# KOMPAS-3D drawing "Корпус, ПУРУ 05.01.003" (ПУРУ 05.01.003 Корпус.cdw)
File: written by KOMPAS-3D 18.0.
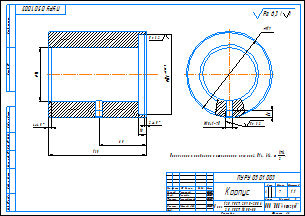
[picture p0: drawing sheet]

Sheet 1: A3, landscape

Document properties: Автор: cons; Полное имя файла: D:\Град\ПУРУ 00.00.000 Установка пусковая ручная Элия-Р\ПУРУ 05.00.000 Корпус\ПУРУ 05.01.000 Обойма\Чертежи\ПУРУ 05.01.003 Корпус.cdw; Масса: 6.98161; Параметр неуказанной шероховатости: Ra 6,3

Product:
- Part/product: Корпус  | designation ПУРУ 05.01.003
    Материал: Круг$d120 ГОСТ 2590-2006;20 ГОСТ 1050-88$ (density 7859 kg/m3)
    Масса: 6.79078
    Раздел спецификации: Детали
    Форматы листов документа: A3
    source file: ..\ПУРУ 05.01.003 Корпус.m3d, ПУРУ 05.01.003 Корпус.cdw
- Part/product: Корпус  | designation ПУРУ 05.01.003
    Материал: Круг$d120 ГОСТ 2590-2006;20 ГОСТ 1050-88$ (density 7859 kg/m3)
    Масса: 6.98161
    Раздел спецификации: Детали
    Форматы листов документа: A3

Table, sheet 1:
  0;Material:V399CD8922A934364BF9D3DB1A16B3F75;Sortament:V6A25FA24F2024846A417965BB2EC510D^SortamentEx:VAF31E2474CC111D7A5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
Title block, sheet 2: Наименование: Корпус; designation: ПУРУ 05.01.003; Материал: Круг 120 ГОСТ 2590-2006 20 ГОСТ 1050-88; Масса: 7; sheet number: 1; organisation: ООО "НПЦ"Антиград"; Форматы листов документа: A3; revision letter: А; stored path: D:\РУ 00.00.000 Установка противоградовая ручная\РУ 05.00.000 Корпус\РУ 05.01.000 Обойма\Чертежи\РУ 05.01.003 Корпус.cdw; Разработал: Грицунов; Проверил: Налоева; Т. контр.: Семеновский; Н. контр.: Абшаев А.М.; Разработал, date: 06.04.2017; Проверил, date: 06.04.2017; Т. контр., date: 06.04.2017; Н. контр., date: 06.04.2017

Views: Вид 1, Местный разрез 1, Сверху, Проекционный вид 2
Referenced files in D:\Град\ПУРУ 00.00.000 Установка пусковая ручная Элия-Р\ПУРУ 05.00.000 Корпус\ПУРУ 05.01.000 Обойма\: ПУРУ 05.01.003 Корпус.m3d
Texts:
  Ra 3,2
  Ra 6,3
  Ra 6,3 ( )
Dimensions and other numbers on the sheet: 74; 110; 10; 2; 65; 135; 4; 119; 1:1; 1; 7; 06.04.2017

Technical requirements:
  Неуказанные предельные отклонения размеров: H14, h14,    IT14 2 .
